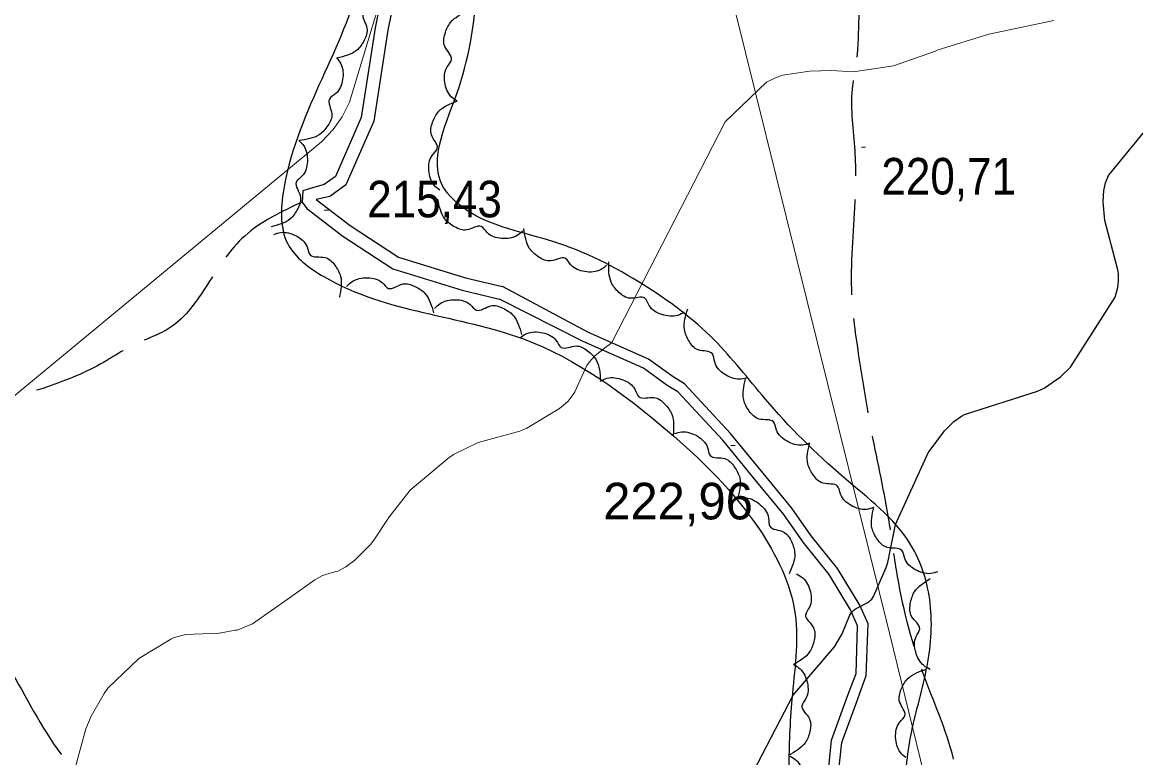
# Model space of a CAD drawing. Extents: x 480269 to 484877, y 4383588 to 4386804.
# Drawn here: x 482971.7 to 483238.1, y 4385554.9 to 4385730.7 of the extents above; entities that cross this region are included whole.
import ezdxf

# ---------------------------------------------------------------- set-up
doc = ezdxf.new("R2010")
doc.units = 0
doc.header["$LTSCALE"] = 3.8
doc.linetypes.add('LONG_DASHED', pattern=[7.5, 6, -1.5])
for name, color, linetype, lineweight in [('27', 7, 'Continuous', 25), ('38', 7, 'Continuous', 25), ('51', 7, 'Continuous', 13), ('7', 7, 'Continuous', 13), ('8', 7, 'Continuous', 25), ('9', 7, 'Continuous', 13)]:
    doc.layers.add(name, color=color, linetype=linetype, lineweight=lineweight)

msp = doc.modelspace()

# ---------------------------------------------------------------- linework, layer by layer
at = {"layer": '27'}
for points in [[(483231.2, 4385389.63), (483227.44, 4385405.62), (483221.8, 4385432.89), (483216.16, 4385454.52), (483213.34, 4385472.39), (483206.76, 4385488.37), (483202.06, 4385497.78), (483193.6, 4385515.64), (483186.08, 4385531.63), (483183.26, 4385543.86), (483184.2, 4385559.84), (483187.96, 4385575.83), (483188.9, 4385591.82), (483184.2, 4385605.92), (483168.22, 4385621.91), (483149.42, 4385640.72), (483137.2, 4385654.83), (483120.28, 4385667.99), (483098.66, 4385678.34), (483077.99, 4385685.86), (483072.35, 4385691.5), (483076.11, 4385715.01), (483081.75, 4385762.97), (483085.51, 4385790.24), (483086.45, 4385812.81), (483082.69, 4385831.62), (483068.59, 4385843.85), (483053.55, 4385846.67), (483034.75, 4385843.85), (483023.47, 4385846.67), (483015.01, 4385863.6), (483002.79, 4385900.27), (483004.67, 4385919.08), (483018.77, 4385934.13), (483062.95, 4385960.46), (483103.36, 4385984.91), (483124.04, 4385997.13), (483142.84, 4385999.02), (483156.21, 4386009.89)], [(482599.89, 4385643.3), (482628.86, 4385671.49), (482714.99, 4385745.13), (482794.85, 4385810.14), (482867.67, 4385855.58), (482941.27, 4385895.53), (482964.76, 4385912.76), (482973.37, 4385911.19), (482981.98, 4385879.86), (482998.42, 4385827.38), (483006.25, 4385814.84), (483025.83, 4385810.93), (483050.88, 4385818.76), (483058.71, 4385808.58), (483056.36, 4385779.59), (483052.45, 4385741.21), (483034.44, 4385691.86), (483035.22, 4385677.76), (483043.84, 4385669.93), (483091.6, 4385655.04), (483126.05, 4385633.11), (483147.97, 4385609.61), (483156.58, 4385589.25), (483155.8, 4385568.88), (483155.02, 4385552.43), (483155.02, 4385532.85), (483155.02, 4385519.53), (483152.67, 4385510.13)], [(483053.96, 4385742.78), (483055.12, 4385741.44), (483055.93, 4385737.73), (483054.65, 4385734.26), (483053.23, 4385732.78), (483054.16, 4385729.34), (483053.5, 4385726.43), (483051.67, 4385724.03), (483047.06, 4385722.2)], [(483075.75, 4385711.89), (483074.33, 4385712.96), (483072.78, 4385716.42), (483073.32, 4385720.07), (483074.4, 4385721.82), (483072.78, 4385724.99), (483072.83, 4385727.97), (483074.13, 4385730.7), (483078.26, 4385733.44)], [(483046.9, 4385722.26), (483047.92, 4385720.81), (483048.35, 4385717.04), (483046.73, 4385713.73), (483045.17, 4385712.39), (483045.75, 4385708.88), (483044.8, 4385706.05), (483042.73, 4385703.85), (483037.95, 4385702.49)], [(483071.62, 4385690.58), (483070.28, 4385691.74), (483068.98, 4385695.31), (483069.77, 4385698.91), (483070.98, 4385700.58), (483069.59, 4385703.85), (483069.85, 4385706.83), (483071.34, 4385709.46), (483075.66, 4385711.89)], [(483037.87, 4385702.52), (483039.05, 4385701.19), (483039.9, 4385697.49), (483038.66, 4385694.01), (483037.26, 4385692.51), (483038.23, 4385689.09), (483037.61, 4385686.17), (483035.8, 4385683.75), (483031.21, 4385681.86)], [(483091.46, 4385680.88), (483090.08, 4385679.75), (483086.35, 4385679.07), (483082.93, 4385680.45), (483081.49, 4385681.91), (483078.03, 4385681.09), (483075.14, 4385681.84), (483072.8, 4385683.75), (483071.11, 4385688.42)], [(483031.85, 4385680.02), (483033.55, 4385680.5), (483037.25, 4385679.66), (483039.85, 4385677.04), (483040.6, 4385675.12), (483044.1, 4385674.51), (483046.46, 4385672.68), (483047.85, 4385670), (483047.56, 4385665.05)], [(483111.5, 4385672.61), (483110.06, 4385671.58), (483106.29, 4385671.13), (483102.97, 4385672.74), (483101.62, 4385674.29), (483098.12, 4385673.7), (483095.28, 4385674.63), (483093.07, 4385676.7), (483091.69, 4385681.46)], [(483130.08, 4385661.44), (483128.48, 4385660.67), (483124.69, 4385660.87), (483121.68, 4385663.01), (483120.62, 4385664.77), (483117.07, 4385664.77), (483114.43, 4385666.18), (483112.6, 4385668.58), (483112.05, 4385673.51)], [(483049.3, 4385667.54), (483050.6, 4385668.75), (483054.28, 4385669.67), (483057.78, 4385668.51), (483059.31, 4385667.14), (483062.71, 4385668.18), (483065.64, 4385667.61), (483068.1, 4385665.85), (483070.08, 4385661.3)], [(483070.34, 4385662.28), (483071.64, 4385663.49), (483075.31, 4385664.43), (483078.82, 4385663.27), (483080.36, 4385661.91), (483083.76, 4385662.96), (483086.69, 4385662.4), (483089.15, 4385660.65), (483091.14, 4385656.11)], [(483145.01, 4385645.72), (483143.26, 4385645.41), (483139.67, 4385646.62), (483137.35, 4385649.49), (483136.8, 4385651.47), (483133.38, 4385652.44), (483131.22, 4385654.5), (483130.1, 4385657.31), (483130.89, 4385662.2)], [(483090.9, 4385655.41), (483092.42, 4385656.34), (483096.21, 4385656.51), (483099.41, 4385654.67), (483100.64, 4385653.02), (483104.18, 4385653.36), (483106.94, 4385652.22), (483109, 4385650.01), (483110.03, 4385645.16)], [(483109.93, 4385644.94), (483111.57, 4385645.64), (483115.34, 4385645.28), (483118.25, 4385643.01), (483119.23, 4385641.2), (483122.79, 4385641.04), (483125.36, 4385639.52), (483127.08, 4385637.04), (483127.42, 4385632.09)], [(483160.05, 4385630.09), (483158.33, 4385629.64), (483154.65, 4385630.58), (483152.12, 4385633.27), (483151.42, 4385635.2), (483147.93, 4385635.9), (483145.62, 4385637.79), (483144.29, 4385640.5), (483144.71, 4385645.44)], [(483127.73, 4385632.41), (483129.46, 4385632.83), (483133.12, 4385631.84), (483135.61, 4385629.12), (483136.28, 4385627.18), (483139.76, 4385626.43), (483142.04, 4385624.5), (483143.33, 4385621.77), (483142.84, 4385616.83)], [(483175.39, 4385614.74), (483173.67, 4385614.3), (483169.99, 4385615.23), (483167.46, 4385617.92), (483166.76, 4385619.85), (483163.27, 4385620.55), (483160.96, 4385622.44), (483159.63, 4385625.15), (483160.05, 4385630.1)], [(483143.05, 4385616.95), (483144.83, 4385617.05), (483148.25, 4385615.42), (483150.21, 4385612.3), (483150.53, 4385610.27), (483153.81, 4385608.9), (483155.71, 4385606.6), (483156.49, 4385603.68), (483155.12, 4385598.91)], [(483190.72, 4385599.39), (483189.01, 4385598.95), (483185.33, 4385599.88), (483182.8, 4385602.57), (483182.1, 4385604.5), (483178.61, 4385605.2), (483176.3, 4385607.09), (483174.97, 4385609.81), (483175.39, 4385614.75)], [(483156.9, 4385598.85), (483158.4, 4385597.9), (483160.23, 4385594.58), (483160, 4385590.9), (483159.07, 4385589.07), (483160.94, 4385586.04), (483161.14, 4385583.06), (483160.06, 4385580.24), (483156.17, 4385577.17)], [(483188.88, 4385576.04), (483187.36, 4385576.95), (483185.42, 4385580.21), (483185.53, 4385583.9), (483186.4, 4385585.76), (483184.44, 4385588.72), (483184.14, 4385591.69), (483185.12, 4385594.55), (483188.92, 4385597.74)], [(483156.29, 4385577.16), (483157.76, 4385576.17), (483159.51, 4385572.8), (483159.18, 4385569.12), (483158.2, 4385567.32), (483159.99, 4385564.25), (483160.12, 4385561.27), (483158.97, 4385558.47), (483155, 4385555.5)], [(482987.06, 4385196.22), (482962.01, 4385203.27), (482933.82, 4385208.75), (482918.16, 4385210.32), (482910.33, 4385217.37), (482911.12, 4385227.55), (482911.12, 4385236.17), (482900.16, 4385244), (482857.87, 4385258.89), (482836.73, 4385270.64), (482824.21, 4385265.15), (482832.82, 4385247.14), (482820.29, 4385239.3), (482767.05, 4385239.3), (482715.37, 4385240.87), (482694.23, 4385249.49), (482675.44, 4385265.94), (482679.36, 4385287.09), (482678.57, 4385302.75), (482650.39, 4385311.37), (482636.29, 4385330.17), (482633.95, 4385351.32), (482617.5, 4385368.55), (482588.53, 4385379.52), (482572.87, 4385393.62), (482558.78, 4385411.63), (482539.21, 4385429.65), (482525.9, 4385448.45), (482516.5, 4385468.82), (482492.23, 4385501.72), (482482.83, 4385522.08), (482488.31, 4385537.75), (482533.73, 4385569.87), (482542.34, 4385576.13)], [(483183.07, 4385554.96), (483181.78, 4385556.19), (483180.63, 4385559.8), (483181.57, 4385563.37), (483182.84, 4385564.99), (483181.59, 4385568.31), (483181.97, 4385571.28), (483183.57, 4385573.84), (483187.98, 4385576.1)], [(483546.8, 4385573.01), (483530.82, 4385569.72), (483504.5, 4385557.5), (483496.51, 4385547.62), (483497.92, 4385533.98), (483509.2, 4385521.29), (483517.19, 4385516.59), (483525.65, 4385519.41), (483535.05, 4385523.64), (483540.22, 4385520.82), (483543.04, 4385508.12), (483538.34, 4385488.84), (483519.07, 4385474.27), (483501.68, 4385462.04), (483485.7, 4385448.88), (483481.94, 4385449.35), (483483.82, 4385456.4), (483491.34, 4385463.45), (483493.69, 4385472.39), (483482.41, 4385488.84), (483469.72, 4385479.44), (483457.5, 4385473.8), (483447.16, 4385476.15), (483435.41, 4385469.57), (483432.12, 4385452.64), (483431.65, 4385426.31), (483427.89, 4385415.96), (483416.61, 4385410.32), (483407.68, 4385404.21), (483394.53, 4385402.8), (483381.37, 4385399.03), (483373.85, 4385390.57), (483366.33, 4385379.29), (483360.69, 4385372.7), (483348.47, 4385369.41), (483324.97, 4385367.06), (483298.65, 4385356.72), (483277.03, 4385345.43), (483258.23, 4385329.91), (483253.06, 4385332.26), (483259.17, 4385339.32), (483268.1, 4385347.78), (483265.28, 4385357.19), (483251.65, 4385366.59), (483243.66, 4385376.46), (483231.44, 4385369.41), (483229.09, 4385383.05), (483230.97, 4385390.1)], [(483155.02, 4385555.49), (483156.55, 4385554.59), (483158.49, 4385551.33), (483158.38, 4385547.64), (483157.51, 4385545.78), (483159.48, 4385542.82), (483159.78, 4385539.85), (483158.8, 4385536.99), (483155.01, 4385533.79)]]:
    msp.add_spline(points, degree=3, dxfattribs=at)
at = {"layer": '38'}
for points in [[(483060.12, 4385749.18), (483056.15, 4385729.4), (483052.8, 4385708), (483046.62, 4385693.9), (483043.9, 4385691.93), (483040.31, 4385690.93), (483038.84, 4385690.43), (483038.66, 4385687.78), (483039.79, 4385686.22), (483048.38, 4385679.64), (483060.36, 4385671.79), (483076.96, 4385666.68), (483085.86, 4385664.59)], [(483063.12, 4385748.44), (483059.19, 4385728.85), (483055.79, 4385707.12), (483049.11, 4385691.89), (483045.26, 4385689.1), (483042.03, 4385688.4), (483050.17, 4385682.16), (483061.68, 4385674.62), (483077.77, 4385669.66), (483086.57, 4385667.6)], [(483167.12, 4385552.72), (483167.73, 4385558.57), (483171.55, 4385569.03), (483173.61, 4385574.55), (483174.02, 4385586.92), (483172.07, 4385591.43), (483166.75, 4385600.15), (483160.45, 4385607.94), (483155.82, 4385614.59), (483148.91, 4385622.95), (483141.14, 4385632.47), (483130.12, 4385644.29), (483127.38, 4385645.98), (483121.53, 4385650.23), (483107.02, 4385656.65), (483086.57, 4385667.6)], [(483164.63, 4385552.7), (483165.3, 4385559.13), (483169.23, 4385569.89), (483171.15, 4385575.04), (483171.53, 4385586.45), (483169.87, 4385590.29), (483164.73, 4385598.72), (483158.47, 4385606.45), (483153.85, 4385613.09), (483147, 4385621.38), (483139.28, 4385630.84), (483128.54, 4385642.36), (483126, 4385643.93), (483120.29, 4385648.08), (483105.89, 4385654.45), (483085.86, 4385664.59)]]:
    msp.add_lwpolyline(points, dxfattribs=at)
at = {"layer": '38', "linetype": 'LONG_DASHED'}
for points in [[(483222.84, 4385328.78), (483233.49, 4385331.65), (483248.44, 4385336.61), (483252.54, 4385340.94), (483258.88, 4385354.18), (483261.76, 4385364.09), (483264.07, 4385370.4), (483271.55, 4385381.16), (483280.42, 4385394.23), (483287.47, 4385408.23), (483295.91, 4385425.29), (483304.52, 4385439.96), (483308.91, 4385446.59), (483318.63, 4385460.51), (483325.16, 4385473.38), (483329.03, 4385484.99), (483336.9, 4385500.43), (483342.08, 4385509.3), (483351.29, 4385526.25), (483356.88, 4385535.07), (483367.82, 4385552.46), (483372.61, 4385560.56), (483384.55, 4385574.31), (483394.22, 4385589.19), (483401.11, 4385600.15), (483408.96, 4385613.82), (483416.11, 4385628.46), (483421.62, 4385644.25), (483425.26, 4385652.82), (483437.44, 4385668.5), (483447.61, 4385682.66), (483455.49, 4385695.61), (483457.94, 4385709.1), (483457.8, 4385712.22), (483460.32, 4385716.64), (483471.95, 4385728.32), (483483.41, 4385737.85), (483491.91, 4385744.84), (483502.88, 4385754.26), (483511.53, 4385762), (483517.86, 4385770.14), (483520.82, 4385773.68), (483521.2, 4385789.84), (483522.3, 4385808.2), (483521.83, 4385825.17), (483522.61, 4385837.11), (483524.33, 4385844.04), (483529.61, 4385862.88), (483530.12, 4385879.57), (483529.5, 4385895.4), (483531.44, 4385911.89), (483533.11, 4385922.24), (483534.94, 4385934.41), (483535.75, 4385947.11), (483535.49, 4385954.95), (483538.08, 4385971.48), (483542.8, 4385983), (483551.34, 4385997.49), (483555.36, 4386004.16), (483555.47, 4386004.25)], [(483269.19, 4385377.79), (483265.83, 4385379.76), (483259.03, 4385384.12), (483248.33, 4385390.08), (483241.93, 4385401.56), (483240.31, 4385411.32), (483239.53, 4385423.1), (483237.61, 4385429.2), (483228.77, 4385444.16), (483215.59, 4385471.64), (483211.39, 4385484.05), (483206.78, 4385496.53), (483203.95, 4385506.6), (483198.79, 4385527.78), (483197.64, 4385533.81), (483194.47, 4385554.66), (483187.12, 4385575.33), (483180.81, 4385599.81), (483178.92, 4385612.27), (483174.66, 4385634.07), (483172.09, 4385649.52), (483170.18, 4385665.56), (483170.94, 4385687.86), (483170.82, 4385701.87), (483170.52, 4385716.56), (483170.83, 4385718.14), (483172.28, 4385738.14), (483175.1, 4385763.48), (483174.2, 4385772.45), (483177.9, 4385781.99), (483183.14, 4385788.4), (483185.49, 4385797.11), (483184.14, 4385804.05), (483177.92, 4385810.59), (483174.55, 4385813.49), (483148.28, 4385826.01)], [(483038.66, 4385687.78), (483024.92, 4385679.64), (483015.99, 4385668.06), (483007.11, 4385657.76), (482998.61, 4385653.73), (482991.14, 4385649.44), (482977.76, 4385643.6), (482959.38, 4385639.1), (482946.65, 4385636.93), (482937.49, 4385634.45), (482930.9, 4385633.45)], [(482931.15, 4385616.32), (482932.73, 4385612.59), (482941.3, 4385604.13), (482954.85, 4385594.15), (482969.35, 4385575.1), (482981.87, 4385554.7), (482987.87, 4385547.86), (482999.65, 4385533.33), (483012.88, 4385522.1), (483024.16, 4385518.63), (483043.21, 4385517.93), (483056.01, 4385517.57), (483060.31, 4385517.38), (483070.36, 4385513.78)]]:
    msp.add_spline(points, degree=3, dxfattribs=at)
at = {"layer": '51'}
msp.add_lwpolyline([(483240.31, 4385333.5), (483213.63, 4385444.02), (483179.14, 4385584.7), (483139.77, 4385743.55), (483119.86, 4385829.82)], dxfattribs=at)
at = {"layer": '7'}
for p, q in [((483172.44, 4385700.88), (483173.44, 4385700.88)), ((483043.96, 4385685.83), (483044.96, 4385685.83)), ((483141.23, 4385629.6), (483142.23, 4385629.6))]:
    msp.add_line(p, q, dxfattribs=at)
at = {"layer": '8'}
msp.add_lwpolyline([(483146.67, 4385551.8), (483156.15, 4385569.87), (483166.03, 4385581.41), (483167.85, 4385584.54), (483169.6, 4385588.88), (483170.06, 4385589.64), (483170.7, 4385590.26), (483171.15, 4385590.58), (483174.1, 4385592.15), (483174.63, 4385592.58), (483174.9, 4385592.85), (483175.34, 4385593.43), (483178.35, 4385600.38), (483178.75, 4385601.58), (483180.58, 4385610.65), (483188.37, 4385627.85), (483192.3, 4385633.06), (483194.56, 4385635.32), (483196.37, 4385636.6), (483197.08, 4385636.98), (483214.56, 4385642.57), (483216.16, 4385643.31), (483220.07, 4385646), (483222.47, 4385648.26), (483233.14, 4385665.04), (483233.75, 4385667.32), (483233.96, 4385668.84), (483233.93, 4385670.6), (483233.79, 4385671.54), (483230.68, 4385683.34), (483230.27, 4385687.83), (483230.43, 4385690.53), (483230.85, 4385692.38), (483231.52, 4385694.08), (483242.69, 4385707.73)], dxfattribs=at)
at = {"layer": '9'}
for points in [[(482964.45, 4385637.04), (483043.26, 4385702.2), (483046.05, 4385705.15), (483048.24, 4385708.11), (483049.99, 4385711.61), (483060.24, 4385745.78)], [(483218.44, 4385731.15), (483202.94, 4385727.92), (483190.55, 4385724.07), (483189.91, 4385723.76), (483180.08, 4385720.36), (483170.51, 4385718.88), (483165.17, 4385719.19), (483160.1, 4385719.08), (483153.59, 4385718.08), (483151.85, 4385717.5), (483149.71, 4385716.45), (483139.84, 4385706.94), (483139.83, 4385706.94)], [(483139.83, 4385706.94), (483112.77, 4385654.17), (483112.13, 4385653.64), (483111.69, 4385653.37), (483108.71, 4385650.98), (483107.39, 4385649.56), (483107.32, 4385649.45), (483107.34, 4385649.42), (483107.33, 4385649.41), (483107.28, 4385649.38), (483107.17, 4385649.26), (483106.79, 4385648.7), (483103.92, 4385642.42), (483103.48, 4385641.72), (483102.3, 4385640.2), (483101.66, 4385639.57), (483100.21, 4385638.44), (483092.39, 4385633.74), (483090.74, 4385633.02), (483080.73, 4385630.29), (483074.9, 4385627.44), (483074.72, 4385627.29), (483073.92, 4385626.74), (483064.49, 4385618.89), (483059.28, 4385612.29), (483059.2, 4385612.15), (483055.77, 4385606.96), (483054.97, 4385605.93), (483051.27, 4385602.18), (483049.09, 4385600.54), (483047.2, 4385599.54), (483046.68, 4385599.47), (483043.54, 4385598.45), (483041.67, 4385597.49), (483035.91, 4385593.28), (483026.8, 4385586.97), (483023.13, 4385585.44), (483022.82, 4385585.39), (483022.6, 4385585.38), (483018.86, 4385584.69), (483018.85, 4385584.69), (483018.8, 4385584.7), (483010.87, 4385584.35), (483008.07, 4385583.64), (483007.27, 4385583.27), (482999.59, 4385578.62), (482992.16, 4385571.52), (482991.26, 4385570.31), (482988.16, 4385564.86), (482986.9, 4385561.8), (482982.78, 4385546.63)]]:
    msp.add_lwpolyline(points, dxfattribs=at)

# ---------------------------------------------------------------- texts
at = {"layer": '7', "width": 0.9}
for s, p in [('220,71', (483177.22, 4385689.57)), ('215,43', (483054.22, 4385684.11))]:
    msp.add_text(s, height=8.75, dxfattribs=at).set_placement(p)
at = {"layer": '7'}
msp.add_text('222,96', height=8.75, dxfattribs=at).set_placement((483110.68, 4385611.9))

doc.saveas('drawing.dxf')
